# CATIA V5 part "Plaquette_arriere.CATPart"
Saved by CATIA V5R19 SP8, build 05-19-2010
Part number: plaquette arrière
Bounding box of the stored display mesh (mm): x -1 to 18.5, y 0 to 17.494, z -2.25 to 0
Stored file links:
  C:\Users\Arthur\Desktop\Catia parts\Plaquette_arriere.CATPart
  C:\Users\Arthur\Desktop\Catia parts\Culasse.CATPart
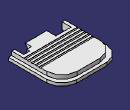
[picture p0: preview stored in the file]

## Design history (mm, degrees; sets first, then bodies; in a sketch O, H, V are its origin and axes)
Body1 (main body)
  Sketch1 on xy-plane, origin (0, 0, 0), H (1, 0, 0), V (0, 1, 0)
    construction line L1 through (0, 0) direction (1, 0)
    construction line L2 through (0, 6.1676) direction (0, 1)
    line L3 (5, 16.5) -> (12.5, 16.5)
    line L4 (0, 0) -> (0, 11.5)
    line L5 (17.5, 0) -> (17.5, 11.5)
    point P1 (8.75, 16.5)
    point P2 (17.5, 5.75)
    point P3 (17.5, 16.5)
    arc A1 centre (12.5, 11.5) radius 5 from (12.5, 16.5) to (17.5, 11.5) cw
    point P4 (0, 16.5)
    arc A2 centre (5, 11.5) radius 5 from (5, 16.5) to (0, 11.5) ccw
    point P5 (0, 0)
    point P6 (17.5, 0)
    line L6 (17.5, 0) -> (16.5, 0)
    line L7 (16.5, 0) -> (16.5, 3)
    line L8 (16.5, 3) -> (14.5, 3)
    line L9 (14.5, 3) -> (14.5, 2)
    line L10 (14.5, 2) -> (13, 2)
    line L11 (13, 2) -> (13, 0)
    line L12 (0, 0) -> (1, 0)
    line L13 (1, 0) -> (1, 3)
    line L14 (1, 3) -> (6, 3)
    line L15 (6, 3) -> (6, 0)
    line L16 (6, 0) -> (13, 0)
    axis line L17 (-10, 25.5) -> (30, 25.5)
    radius A1 = 5
    radius A2 = 5
    distance L5 L4 = 17.5
    length L4 = 11.5
    length L6 = 1
    length L7 = 3
    length L8 = 2
    length L9 = 1
    length L10 = 1.5
    length L12 = 1
    length L13 = 3
    length L14 = 5
    distance L1 L17 = 25.5
    horizontal: L3 L1, L6 H, L8 H, L10 H, L12 H, L14 H, L16 H, L17 H
    vertical: L4 L2, L5 L2, L7 V, L9 V, L11 V, L13 V, L15 V
    midpoint: P1 L3, P2 L5
    coincidence: L3 P3, L5 P3, L3 P4, L4 P4, L4 L2, L2 V, L1 H, P6 L1, P5 O, L16 L1
    tangency: A1 L3, A1 L5, A2 L3, A2 L4
  Pad1: profile Sketch1, direction (0, 0, -1), length 2.25
  Sketch2 on end face of Pad1, origin (0, 0, -2.25), H (1, 0, 0), V (0, -1, 0)
    point P1 (-1, 0)
    line L1 (18.5, 0) -> (18.5, -12.5)
    line L2 (-1, -12.5) -> (-1, 0)
    point P2 (18.5, 0)
    point P3 (18.5, -12.5)
    point P4 (-1, -12.5)
    line L3 (-1, 0) -> (1, 0)
    line L4 (1, 0) -> (1, -5)
    line L5 (1, -5) -> (6, -5)
    line L6 (6, -5) -> (6, 0)
    line L7 (6, 0) -> (13, 0)
    line L8 (13, 0) -> (13, -4)
    line L9 (13, -4) -> (14.5, -4)
    line L10 (14.5, -4) -> (14.5, -5)
    line L11 (14.5, -5) -> (16.5, -5)
    line L12 (16.5, -5) -> (16.5, 0)
    line L13 (18.5, 0) -> (16.5, 0)
    point P15 (4, -12.5)
    point P16 (13.5, -12.5)
    line L14 (13.75, -17.4937) -> (3.75, -17.4937)
    point P17 (13.75, -17.4937)
    point P18 (3.75, -17.4937)
    construction line L15 (8.75, -30) -> (8.75, 10)
    reference projected line E1 (0, 0) -> (0, -12.5) from edge [face of Pad1 from Sketch1.L4 | end face of Pad1]
    reference projected line E2 (17.5, -12.5) -> (17.5, 0) from edge [face of Pad1 from Sketch1.L5 | end face of Pad1]
    arc A1 centre (13.5, -12.5) radius 5 from (13.75, -17.4937) to (18.5, -12.5) ccw
    point P21 (18.5, -12.5)
    arc A2 centre (4, -12.5) radius 5 from (-1, -12.5) to (3.75, -17.4937) ccw
    point P22 (3.75, -17.4937)
    axis line L16 (20, -12.5) -> (-10, -12.5)
    distance V L2 = 1
    length L3 = 2
    length L4 = 5
    length L5 = 5
    length L7 = 7
    length L8 = 4
    length L9 = 1.5
    length L10 = 1
    length L11 = 2
    length L13 = 2
    radius A2 = 5
    distance P4 P1 = 12.5
    length L14 = 10
    vertical: L1 V, L2 V, L4 V, L6 V, L8 V, L10 V, L12 V, L15 V
    horizontal: L3 H, L5 H, L7 H, L9 H, L11 H, L13 H, L14 H, L16 H
    coincidence: L7 L3, P2 L3, L3 H, P21 P3, P22 P18, P4 L16, P3 L16, P16 L16, P15 L16
    symmetry: E1 E2 L15, P17 P18 L15
  Pad2: profile Sketch2, direction (0, 0, 1), length 1
  Sketch3 on start face of Pad1, origin (0, 0, 0), H (1, 0, 0), V (0, 1, 0)
    line L1 (0, 4.5) -> (17.5, 4.5)
    line L2 (17.5, 4.5) -> (17.5, 4)
    line L3 (17.5, 4) -> (0, 4)
    line L4 (0, 4) -> (0, 4.5)
    axis line L5 (8.75, 0) -> (8.75, 20)
    reference projected line E1 (18.5, 19.5) -> (18.5, 0) from edge [end face of Pad2 | face of Pad2 from Sketch2.L1]
    reference projected line E2 (-1, 0) -> (-1, 19.5) from edge [end face of Pad2 | face of Pad2 from Sketch2.L2]
    reference projected line E3 (6, 3) -> (1, 3) from edge [face of Pad3 | face of Pad3]
    reference projected line E4 (0, 0) -> (0, 12.5) from edge [face of Pad3 | face of Pad3]
    length L2 = 0.5
    distance L3 E3 = 1
    horizontal: L1 H, L3 H
    vertical: L2 V, L4 V, L5 V
    symmetry: E1 E2 L5, L2 L4 L5
    coincidence: L4 E4
  Pocket1: profile Sketch3, direction (0, 0, -1), length 0.1
  RectPattern1: of Pocket1, direction 1 instances 1, spacing 20, along start face of Pad1, direction 2 instances 5, spacing 1.25, along start face of Pad1
  Chamfer1: length 2, angle 45, on edge [face of Pad2 | face of Pad2]
  Sketch4 on face of Pad2, origin (0, 0, -2.25), H (1, 0, 0), V (0, -1, 0)
    circle A1 centre (8.75, -8.5) radius 6
    point P1 (8.75, -8.5)
    axis line L1 (8.75, 4.2983) -> (8.75, -20)
    reference projected line E1 (18.5, -12.5) -> (18.5, 0) from edge [face of Pad2 from Sketch2.L1 | start face of Pad2]
    reference projected line E2 (-1, 0) -> (-1, -12.5) from edge [face of Pad2 from Sketch2.L2 | start face of Pad2]
    reference projected line E3 (5, -16.5) -> (12.5, -16.5) from edge [start face of Pad1 | face of Pad1 from Sketch1.L3]
    radius A1 = 6
    distance P1 E3 = 8
    vertical: L1 V
    coincidence: P1 L1
    symmetry: E1 E2 L1
  Pocket2: profile Sketch4, direction (0, 0, 1), length 1.5
  Sketch5 on start face of Pad1, origin (0, 0, 0), H (1, 0, 0), V (0, 1, 0)
    construction line L1 through (0, 0) direction (1, 0)
    construction line L2 through (0, 6.1676) direction (0, 1)
    line L3 (6, 18.5) -> (11.5, 18.5)
    line L4 (0, 0) -> (0, 12.5)
    line L5 (17.5, 0) -> (17.5, 12.5)
    point P1 (8.75, 18.5)
    point P2 (17.5, 6.25)
    point P3 (17.5, 18.5)
    arc A1 centre (11.5, 12.5) radius 6 from (11.5, 18.5) to (17.5, 12.5) cw
    point P4 (0, 18.5)
    arc A2 centre (6, 12.5) radius 6 from (6, 18.5) to (0, 12.5) ccw
    point P5 (0, 0)
    point P6 (17.5, 0)
    line L6 (17.5, 0) -> (16.5, 0)
    line L7 (16.5, 0) -> (16.5, 5)
    line L8 (16.5, 5) -> (14.5, 5)
    line L9 (14.5, 5) -> (14.5, 4)
    line L10 (14.5, 4) -> (13, 4)
    line L11 (13, 4) -> (13, 0)
    line L12 (0, 0) -> (1, 0)
    line L13 (1, 0) -> (1, 5)
    line L14 (1, 5) -> (6, 5)
    line L15 (6, 5) -> (6, 0)
    line L16 (6, 0) -> (13, 0)
    radius A1 = 6
    radius A2 = 6
    distance L5 L4 = 17.5
    length L4 = 12.5
    length L6 = 1
    length L7 = 5
    length L8 = 2
    length L9 = 1
    length L10 = 1.5
    length L12 = 1
    length L13 = 5
    length L14 = 5
    horizontal: L3 L1, L6 H, L8 H, L10 H, L12 H, L14 H, L16 H
    vertical: L4 L2, L5 L2, L7 V, L9 V, L11 V, L13 V, L15 V
    midpoint: P1 L3, P2 L5
    coincidence: L3 P3, L5 P3, L3 P4, L4 P4, L4 L2, L2 V, L1 H, P6 L1, P5 O
    tangency: A1 L3, A1 L5, A2 L3, A2 L4
  Pad3: profile Sketch5, direction (0, 0, -1), length 2.25
Current feature: Pocket2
